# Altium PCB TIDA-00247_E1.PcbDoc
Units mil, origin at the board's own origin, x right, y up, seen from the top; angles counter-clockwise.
Board outline 550 x 2250 mil, 4 copper layers (Top Layer, GND, VCC, Bottom Layer), stack 90 mil thick; 72 components, 30 nets, 175 pads, 76 vias.
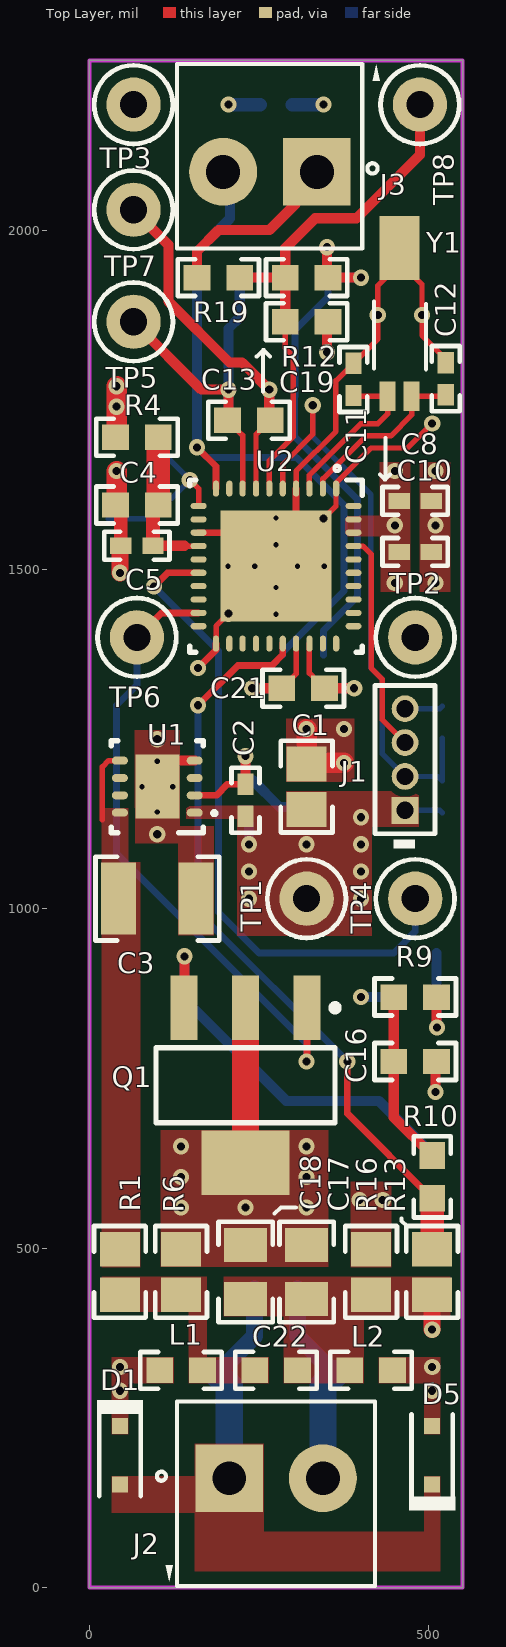
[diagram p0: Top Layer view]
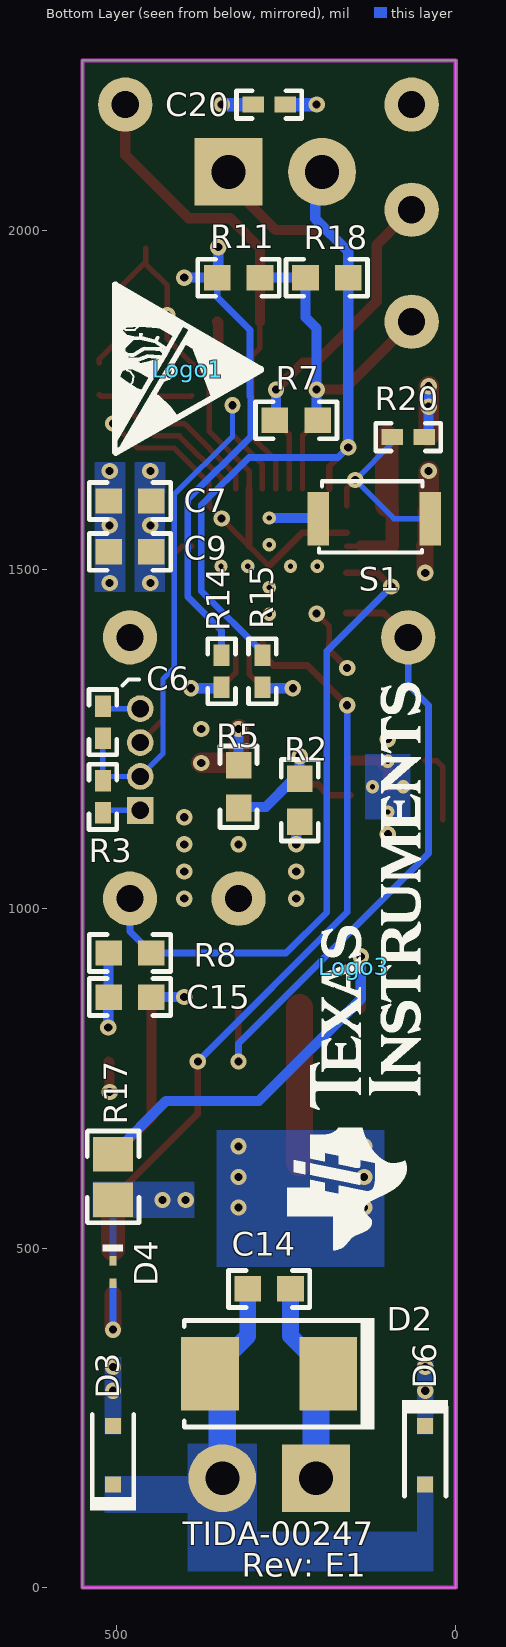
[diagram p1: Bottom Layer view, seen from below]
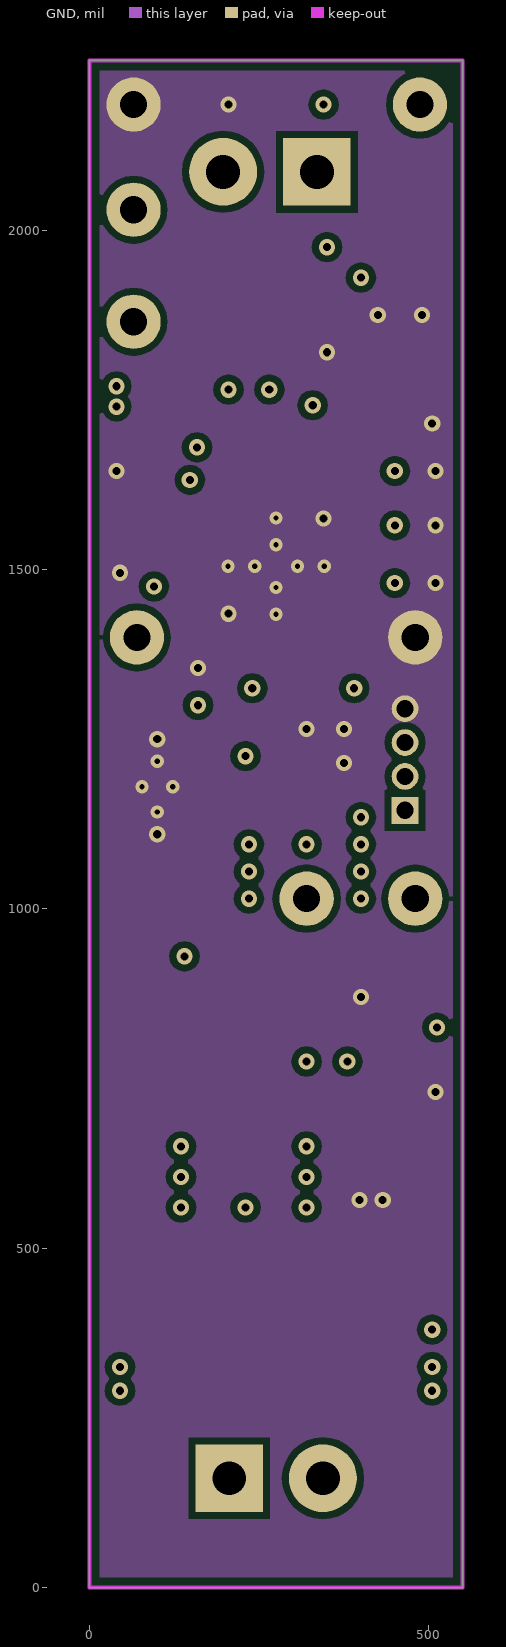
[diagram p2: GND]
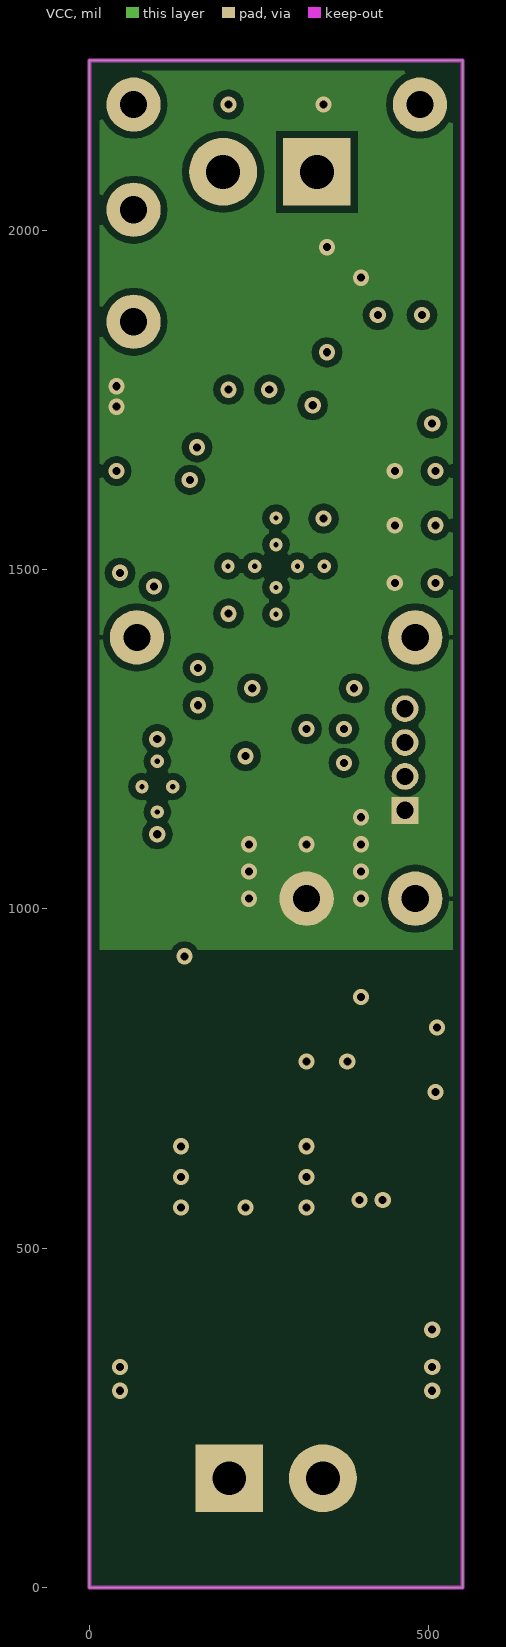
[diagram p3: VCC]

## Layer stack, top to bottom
Top Layer: signal copper 1.4
Dielectric: core 59.2, FR-4, Dk 4.8
GND: signal copper 1.4
Dielectric: prepreg 12.6, FR-4, Dk 4.8
VCC: signal copper 1.4
Dielectric: core 12.6, FR-4, Dk 4.8
Bottom Layer: signal copper 1.4

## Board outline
0,0 550,0 550,2250 0,2250

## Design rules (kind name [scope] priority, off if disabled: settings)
Clearance [All] p1: gap=10
DiffPairsRouting [All] p1: maxlimit=393.7 minlimit=4.92 mostfreqgap=5.91 maxuncoupledlength=500
FabricationTestPointUsage FabricationTestPointUsage_1 [All] p1: valid=0 allowmultiple=FALSE
FabricationTestpoint FabricationTestpoint_1 [All] p1: side=3 testpointundercomponent=TRUE minsize=40 maxsize=100 preferedsize=60 minholesize=0 maxholesize=40 preferedholesize=32 testpointgrid=1 allowsidetop=TRUE allowsidebottom=TRUE usegrid=TRUE gridtolerance=0.01
HoleSize [All] p1: absolutevalues=TRUE maxlimit=236.22 minlimit=7.87 maxpercent=80.000 minpercent=20.000
HoleSize FabricationTestpoint [All] p2 off: absolutevalues=TRUE maxlimit=100 minlimit=1 maxpercent=80.000 minpercent=20.000
HoleSize FabricationTestPointUsage [All] p3 off: absolutevalues=TRUE maxlimit=100 minlimit=1 maxpercent=80.000 minpercent=20.000
MinimumAnnularRing [All] p1: minimumring=5
PlaneClearance [All] p1: clearance=5
PlaneConnect [All] p1: planeconnectstyle=Direct reliefexpansion=15.75 reliefentries=4 reliefconductorwidth=5.91 reliefairgap=5.91
PolygonConnect [All] p1: connectstyle=Direct reliefconductorwidth=5.91 reliefentries=4 polygonreliefangle="90 Angle" airgapwidth=10
RoutingCorners [All] p1: cornerstyle=45-Degree minsetback=49.21 maxsetback=49.21
RoutingVias [All] p1: holewidth=12 width=24 viastyle="Through Hole" minholewidth=8 minwidth=18 maxholewidth=16 maxwidth=40
SilkscreenOverComponentPads [All] p1: minsilkscreentomaskgap=10
SolderMaskExpansion [All] p1: expansion=2.5
Width [All] p1: maxlimit=100 minlimit=6 preferedwidth=6
20 further rules are at their usual default settings.

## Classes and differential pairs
component class Header: J1
component class Sheet-1: C1 C2 C3 C4 C5 C6 C7 C8 C9 C10 C11 C12 C13 C14 C15 C16 C17 C18 C19 C20 C21 C22 D1 D2 D3 D4 D5 D6 H1 J1 J2 J3 L1 L2 Q1 R1 R2 R3 R4 R5 R6 R7 R8 R9 R10 R11 R12 R13 R14 R15 R16 R17 R18 R19 R20 S1 TP1 TP2 TP3 TP4 TP5 TP6 TP7 TP8 U1 U2 Y1
component class Hardware_ANSI-B: Logo1 ZZ1 ZZ2 ZZ3 ZZ4
component class AssemblyNote: ZZ1 ZZ2 ZZ3 ZZ4
component class Logo: Logo1

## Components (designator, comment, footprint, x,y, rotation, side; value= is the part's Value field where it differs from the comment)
C1 "GRM21BR71A475KA73L" 0805 320,1180 r90 top
C2 "GRM155R70J103KA01D" 0402 230,1160 r90 top
C3 "GRM32MR72A474KA01L" 1210 100,1015 r0 top
C4 "GRM188R71A225KE15D" 0603 70,1595 r180 top
C5 "GRM155R70J104KA01D" 0402 70,1535 r180 top
C6 "GRM155R70J222KA01D" 0402 520,1275 r90 bottom
C7 "GRM188R71A225KE15D" 0603 480,1601 r0 bottom
C8 "GRM155R70J104KA01D" 0402 480,1601 r0 top
C9 "GRM188R71A225KE15D" 0603 480,1526 r0 bottom
C10 "GRM155R70J104KA01D" 0402 480,1526 r0 top
C11 "GRM1555C1H100JA01D" 0402 389,1780 r90 top
C12 "GRM1555C1H100JA01D" 0402 525,1781.26 r90 top
C13 "GRM188R70J224KA88D" 0603 235,1720 r180 top
C14 "CAP, CERM, 0.01uF, 100V, +/-10%, X7R, 0603" 0603 275,440 r0 bottom
C15 "GRM188R70J105KA01D" 0603 480,870 r180 bottom
C16 "GRM188R70J105KA01D" 0603 480,775 r0 top
C17 "08055C105KAT2A" 0805_HV 320,465 r270 top
C18 "08055C103JAT2A" 0805_HV 230,465 r270 top
C19 "C0603C475K9PACTU" 0603 320,1865 r0 top
C20 "GRM155R70J104KA01D" 0402 275,2185 r0 bottom
C21 "GRM188R70J105KA01D" 0603 315,1325 r180 top
C22 "CAP, CERM, 0.01uF, 100V, +/-10%, X7R, 0603" 0603 275,320 r0 top
D1 "BAT46WJ,115" SOD-323F#1 45,195 r270 top
D2 "SM6T39CA" SMB 275,315 r0 bottom
D3 "BAT46WJ,115" SOD-323F#2 505,195 r90 bottom
D4 "ESD9R3.3ST5G" SOD-923 505,465 r270 bottom
D5 "BAT46WJ,115" SOD-323F#1 505,195 r90 top
D6 "BAT46WJ,115" SOD-323F#1 45,195 r270 bottom
J1 "850-10-004-10-001101" Preci-dip_850-xx-004-10-001101 465,1220 r90 top
J2 "ED555/2DS" TERM_BLK_ED555-2DS 206,161 r0 top
J3 "RTD Input" TERM_BLK_ED555-2DS 335,2086 r180 top
L1 "BLM18KG601SN1D" 0603 135,320 r180 top
L2 "BLM18KG601SN1D" 0603 415,320 r0 top
Logo1 "ESD Logo" ESD_Overlay_Medium 395,1795 r270 bottom
Logo3 "Texas Instruments" TI_Stacked_SolderMask_Small 150,915 r90 bottom (schematic designator Logo1)
Q1 "BCP55" SOT-223 230,740 r270 top
R1 "CRCW0805200RFKEA" 0805 45,465 r270 top
R2 "RG1608P-2212-B-T5" 0603 230,1160 r270 bottom
R3 "CRCW040247K0JNED" 0402 520,1165 r270 bottom
R4 "CRCW060310R0FKEA" 0603 70,1695 r180 top
R5 "RG1608P-1242-B-T5" 0603 320,1180 r270 bottom
R6 "CRCW0805100RFKEA" 0805 135,465 r270 top
R7 "RT0603BRD0725K5L" 0603 235,1720 r0 bottom
R8 "RT0603BRD0715K8L" 0603 480,935 r0 bottom
R9 "RT0603BRD0715K8L" 0603 480,870 r180 top
R10 "RT0603BRD07240KL" 0603 505,605 r270 top
R11 "RT0603BRD0710KL" 0603 320,1930 r0 bottom
R12 "RT0603BRD0710KL" 0603 320,1930 r0 top
R13 "RT0805BRD0780K6L" 0805 505,465 r90 top
R14 "CRCW04024K99FKED" 0402 345,1350 r90 bottom
R15 "CRCW04024K99FKED" 0402 285,1350 r90 bottom
R16 "RT0805BRD0740R2L" 0805 415,465 r270 top
R17 "CRCW080520R0FKEA" 0805 505,605 r90 bottom
R18 "RT0603BRD071KL" 0603 190,1930 r0 bottom
R19 "RT0603BRD071KL" 0603 190,1930 r0 top
R20 "CRCW04021M00JNED" 0402 70,1695 r180 bottom
S1 "SKRKAEE010" SW_SKRKAEE010 120,1575 r180 bottom
TP1 "5002" Keystone5002 320,1015 r0 top
TP2 "5001" Keystone5001 480,1400 r0 top
TP3 "5001" Keystone5001 65,2185 r0 top
TP4 "5000" Keystone5000 480,1015 r0 top
TP5 "5000" Keystone5000 65,1865 r0 top
TP6 "5000" Keystone5000 70,1400 r0 top
TP7 "5000" Keystone5000 65,2030 r0 top
TP8 "5000" Keystone5000 487,2185 r0 top
U1 "TPS7A1601DRB" DRB0008B 100,1180 r180 top
U2 "MSP430F2274IRHA" RHA0040B 275,1505 r270 top
Y1 "MS3V-T1R" CRYSTAL-MS3V-T1R 457,1816 r90 top
ZZ1 "This Assembly Note is for PCB labels only" AssemblyNoteLabel 144.43,3724.68 r0 top
ZZ2 "These assemblies are ESD sensitive, ESD precautions shall be observed." AssemblyNote 142.37,3647.98 r0 top
ZZ3 "These assemblies must be clean and free from flux and all contaminants. Use of no clean flux is not acceptable." AssemblyNote 144.39,3796.83 r0 top
ZZ4 "These assemblies must comply with workmanship standards IPC-A-610 Class 2, unless otherwise specified." AssemblyNote 145.73,3859.22 r0 top

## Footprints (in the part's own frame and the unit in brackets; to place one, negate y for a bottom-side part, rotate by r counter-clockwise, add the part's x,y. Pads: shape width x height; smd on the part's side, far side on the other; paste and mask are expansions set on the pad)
0402 [mm] "0402 from SM-752 data"
  rect 0.8x0.6 smd: 1(-0.6,0) 2(0.6,0)
  silkscreen extent -1.22,-0.52 1.22,0.52, body extent -0.55,-0.3 0.55,0.3, height 0.6
0603 [mm] "0603 from SM-752 data"
  rect 1x0.95 smd: 1(-0.8,0) 2(0.8,0)
  silkscreen extent -1.52,-0.69 1.52,0.69, body extent -0.87,-0.47 0.87,0.47, height 0.85
0805 [mm] "0805 from SM-752 data"
  rect 1.3x1.5 smd: 1(-0.85,0) 2(0.85,0)
  silkscreen extent -1.72,-0.97 1.72,0.97, body extent -1.1,-0.72 1.1,0.72, height 1.1
0805_HV [mil] "0805 with 30mil clearance between pads"
  rect 50x63 smd: 1(-40,0) 2(40,0)
  silkscreen extent -74,-40 74,40, body extent -43,-29 43,29, height 43
1210 [mm] "1210 from SM-752 data"
  rect 1.3x2.7 smd: 1(-1.45,0) 2(1.45,0)
  silkscreen extent -2.32,-1.57 2.32,1.57, body extent -1.7,-1.35 1.7,1.35, height 1.35
AssemblyNote [mil] "Assembly Note"
AssemblyNoteLabel [mil] "Assembly Note for PCB Labels"
CRYSTAL-MS3V-T1R [mm]
  rect 1.1x0.6 smd: 1(-1.55,-0.45) 2(-1.55,0.45)
  rect 2.4x1.5 smd: 3(4,0)
DRB0008B [mm] "SON, 8-Leads, Body 3x3mm, Pitch 0.65mm, Thermal Pad 2.4x1.65mm, TI Recommended"
  oval 0.6x0.3 smd: 1(-1.4,0.975) 2(-1.4,0.325) 3(-1.4,-0.325) 4(-1.4,-0.975) 5(1.4,-0.975) 6(1.4,-0.325) 7(1.4,0.325) 8(1.4,0.975)
  rect 1.65x2.4 smd paste-1.2: 9(0,0)
  silkscreen extent -1.73,-1.73 1.73,1.73, body extent -1.57,-1.57 1.58,1.58, height 1.01
ESD_Overlay_Medium [mil]
  silkscreen extent -127,-109 125,110
Keystone5000 [mil] "For Keystone 500x miniature loop terminals"
  round 80 hole 40: 1(0,0)
  silkscreen extent -58,-58 58,58, body extent -49,-49 49,49, height 182
Keystone5001 [mil] "For Keystone 500x miniature loop terminals"
  round 80 hole 40: 1(0,0)
  silkscreen extent -58,-58 58,58, body extent -49,-49 49,49, height 182
Keystone5002 [mil] "For Keystone 500x miniature loop terminals"
  round 80 hole 40: 1(0,0)
  silkscreen extent -58,-58 58,58, body extent -49,-49 49,49, height 182
Preci-dip_850-xx-004-10-001101 [mm] "Preci-dip"
  rect 1x1 hole 0.65: 1(-1.905,0)
  round 1 hole 0.65: 2(-0.635,0) 3(0.635,0) 4(1.905,0)
  silkscreen extent -3.32,-1.12 2.78,1.12, body extent -2.74,-1.1 2.74,1.1, height 5.2
RHA0040B [mm] "QFN, 40-Leads, Body 6x6mm, Pitch 0.5mm, Thermal Pad 4.15 x 4.15mm, TI Recommended"
  oval 0.6x0.23 smd mask+0.07: 1(-2.9,2.25) 2(-2.9,1.75) 3(-2.9,1.25) 4(-2.9,0.75) 5(-2.9,0.25) 6(-2.9,-0.25) 7(-2.9,-0.75) 8(-2.9,-1.25) 9(-2.9,-1.75) 10(-2.9,-2.25) 21(2.9,-2.25) 22(2.9,-1.75) 23(2.9,-1.25) 24(2.9,-0.75) 25(2.9,-0.25) 26(2.9,0.25) 27(2.9,0.75) 28(2.9,1.25) 29(2.9,1.75) 30(2.9,2.25)
  oval 0.23x0.6 smd mask+0.07: 11(-2.25,-2.9) 12(-1.75,-2.9) 13(-1.25,-2.9) 14(-0.75,-2.9) 15(-0.25,-2.9) 16(0.25,-2.9) 17(0.75,-2.9) 18(1.25,-2.9) 19(1.75,-2.9) 20(2.25,-2.9) 31(2.25,2.9) 32(1.75,2.9) 33(1.25,2.9) 34(0.75,2.9) 35(0.25,2.9) 36(-0.25,2.9) 37(-0.75,2.9) 38(-1.25,2.9) 39(-1.75,2.9) 40(-2.25,2.9)
  rect 4.15x4.15 smd paste-2.1 mask+0.07: 41(0,0)
  silkscreen extent -3.22,-3.22 3.22,3.22, body extent -3.08,-3.08 3.08,3.08, height 1.01
SMB [mil] "Molded Diode, 2-Leads, Body 5.4x3.6mm, IPC Medium Density, based on OnSemi component dimensions"
  rect 85x107.99 smd: 1(-87.01,0) 2(87.01,0)
  silkscreen extent -155,-82 125,82, body extent -106,-71 106,71, height 91
SOD-323F#1 [mm] "NXP recommended land pattern"
  rect 0.6x0.6 smd paste+0: 1(-1.1,0) 2(1.1,0)
  silkscreen extent -2.06,-0.86 1.53,0.87, body extent -1.35,-0.67 1.35,0.68, height 0.79
SOD-323F#2 [mm] "NXP recommended land pattern"
  rect 0.6x0.6 smd paste+0: 1(-1.1,0)
  rect 0.6x0.6 smd: 2(1.1,0)
  silkscreen extent -2.07,-0.86 1.53,0.86, body extent -1.35,-0.68 1.35,0.67, height 0.79
SOD-923 [mm] "ON-SEMI"
  rect 0.36x0.25 smd: 1(-0.42,0) 2(0.42,0)
  silkscreen extent -1.02,-0.39 -0.76,0.37, body extent -0.45,-0.35 0.45,0.35, height 0.44
SOT-223 [mm] "SOT223/SC73, 4-Leads, Body 6.5x3.5mm, Pitch 2.3mm, Lead Span 7mm, IPC Medium Density"
  rect 2.4x1 smd: 1(-2.9,2.3) 2(-2.9,0) 3(-2.9,-2.3)
  rect 2.4x3.3 smd: 4(2.9,0)
  silkscreen extent -3.02,-3.35 1.4,3.48, body extent -3.5,-3.25 3.5,3.25, height 1.62
SW_SKRKAEE010 [mm] "Alps recommended land pattern"
  rect 0.8x2 smd: 1(-2.1,0) 2(2.1,0)
  body extent -2.4,-1.45 2.4,1.45, height 1.96
TERM_BLK_ED555-2DS [mil]
  rect 100x100 hole 50: 1(0,0)
  round 100 hole 50: 2(138,0)
  silkscreen extent -94,-159 215,113, body extent -69,-150 207,106, height 323
TI_Stacked_SolderMask_Small [mil]
  silkscreen extent -418,-98 418,98

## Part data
C1: "CAP, CERM, 4.7 µF, 10 V, +/- 10%, X7R, 0805"
C2: "CAP, CERM, 0.01 µF, 6.3 V, +/- 10%, X7R, 0402"
C3: "CAP, CERM, 0.47 µF, 100 V, +/- 10%, X7R, 1210"
C4 C7 C9: "CAP, CERM, 2.2 µF, 10 V, +/- 10%, X7R, 0603"
C5 C8 C10 C20: "CAP, CERM, 0.1 µF, 6.3 V, +/- 10%, X7R, 0402"
C6: "CAP, CERM, 2200pF, 6.3V, +/-10%, X7R, 0402"
C11 C12: "CAP, CERM, 10pF, 50V, +/-5%, C0G/NP0, 0402"
C13: "CAP, CERM, 0.22 µF, 6.3 V, +/- 10%, X7R, 0603"
C14 C22: library part GRM188R72A103KA01D
C15 C16 C21: "CAP, CERM, 1 µF, 6.3 V, +/- 10%, X7R, 0603"
C17: "CAP, CERM, 1uF, 50V, +/-10%, X7R, 0805"
C18: "CAP, CERM, 0.01uF, 50V, +/-5%, X7R, 0805"
C19: "CAP, CERM, 4.7 µF, 6.3 V, +/- 10%, X5R, 0603"
D1 D3 D5 D6: "Diode, Schottky, 100V, 0.25A, SOD-323F"
D2: library part SMBJ40CA-13-F, "TVS DIODE 33.3VWM 69.7VC SMB"
D4: "Diode, TVS, Uni, 3.3V, 0.15W, SOD-923"
J1: "Header, 50mil, 4x1, Gold, TH"
J2: "Terminal Block, 6A, 3.5mm Pitch, 2-Pos, TH"
J3: library part ED555/2DS, "Terminal Block, 6A, 3.5mm Pitch, 2-Pos, TH"
L1 L2: "Ferrite Bead, 600 ohm @ 100MHz, 1.3A, 0603"
Logo1 Logo3: library part TI_Logo, "Texas Instrument Corporate Signature"
Q1: library part "BCP55, Fairchild Semiconductor", "Transistor, NPN, 60 V, 1.5 A, SOT-223"
R1: "RES, 200 ohm, 1%, 0.125W, 0805"
R2: "RES, 22.1 k, 0.1%, 0.1 W, 0603"
R3: "RES, 47k ohm, 5%, 0.063W, 0402"
R4: "RES, 10.0 ohm, 1%, 0.1W, 0603"
R5: "RES, 12.4 k, 0.1%, 0.1 W, 0603"
R6: "RES, 100 ohm, 1%, 0.125W, 0805"
R7: "RES, 25.5 k, 0.1%, 0.1 W, 0603"
R8 R9: "RES, 15.8 k, 0.1%, 0.1 W, 0603"
R10: "RES, 240 k, 0.1%, 0.1 W, 0603"
R11 R12: "RES, 10.0 k, 0.1%, 0.1 W, 0603"
R13: "RES, 80.6k ohm, 0.1%, 0.125W, 0805"
R14 R15: "RES, 4.99 k, 1%, 0.063 W, 0402"
R16: "RES, 40.2, 0.1%, 0.125 W, 0805"
R17: "RES, 20.0 ohm, 1%, 0.125W, 0805"
R18 R19: "RES, 1.00 k, 0.1%, 0.1 W, 0603"
R20: "RES, 1.0 M, 5%, 0.063 W, 0402"
S1: "Switch, Push Button, SMD"
TP1: "Test Point, Miniature, White, TH"
TP2 TP3: "Test Point, Miniature, Black, TH"
TP4 TP5 TP6 TP7 TP8: "Test Point, Miniature, Red, TH"
U1: "60-V, 5-µA IQ, 100-mA, Low-Dropout Voltage Regulator with Enable and Power-Good, DRB0008B"
U2: "16-bit Ultra-Low-Power Microcontroller, 32 KB Flash, 1 K RAM, RHA0040B"
Y1: library part CRYSTAL_MS3V-T1R, "Crystal, Tuning Fork, 30kHz - 200kHz, SMD"
ZZ1: library part AssemblyNoteLabel
ZZ2 ZZ3 ZZ4: library part AssemblyNote

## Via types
v1: diameter 24, hole 12, Top Layer to Bottom Layer, tented both sides, 64 vias
v2: diameter 19.68, hole 7.87, Top Layer to Bottom Layer, tented both sides, 12 vias

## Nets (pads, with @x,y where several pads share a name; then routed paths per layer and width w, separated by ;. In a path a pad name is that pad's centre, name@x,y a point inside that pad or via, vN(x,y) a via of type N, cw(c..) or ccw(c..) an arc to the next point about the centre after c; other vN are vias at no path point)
3.3V: C1.1 C2.1 C7.1 C8.1 C9.1 C10.1 C20.2 J1.1 R2.2 R3.2 R4.2 R11.2 R12.2 R14.2 R20.2 TP1.1 U1.1 U2.38 U2.39 | length 1108.3
  Top Layer w15: R12.2@350,1931.5 v1(350,1975) ; R12.2 v1(400,1930)
  Top Layer w30: R4.2@40,1696.5 v1(40,1740) v1(40,1770)
  Bottom Layer w8: J1.1 516.38,1145 R3.2
  Bottom Layer w10: R14.2 345,1410 395,1460 395,1603.13 302,1696.13 302,1754.18 303,1755.18 303,1853 351.5,1901.5 R11.2
  Bottom Layer w15: v1(40,1770) v1(40,1740) 40,1701.38 R20.2 ; R2.2@230,1130 235,1125 v1(235,1095) ; R11.2@350,1931.5 v1(350,1975) ; R11.2@356.5,1930 v1(400,1930)
  Bottom Layer w20: C20.2 v1(345,2185) ; R11.2@350,1931.5 R11.2
  other v1: 235,1015 400,1015 235,1055 400,1055 320,1095 400,1095 400,1135 450,1480 450,1565 450,1645
ADC_IN: C13.1 R7.2 TP7.1 U2.7 | length 559.6
  Top Layer w8: U2.7 245.47,1698.98 C13.1
  Top Layer w15: TP7.1 116.32,1978.68 116.32,1895 206.32,1805 225,1805 v1(265,1765) 265,1721.5 C13.1
  Bottom Layer w15: v1(265,1765) 265,1721.5 R7.2
AVCC: C4.1 C5.1 R4.1 U2.14 | length 230.7
  Top Layer w8: 140,1535 140.47,1534.53 U2.14
  Top Layer w15: C5.1 140,1535
  Top Layer w20: C5.1 93.62,1587.13 C4.1
  Top Layer w35: C4.1 R4.1
BASE_BJT: Q1.1 TP6.1 U2.19 | length 938.6
  Top Layer w10: TP6.1 106.1,1436.1 U2.19 ; v1(320,775) 320.55,775.55 Q1.1
  Bottom Layer w10: TP6.1 70,1330 40,1300 40,1081.72 320,801.72 v1(320,775)
BRDG_OA0+: C19.1 R12.1 R19.2 TP8.1 U2.6 | length 770.1
  Top Layer w8: U2.6 265.16,1660.48 300.18,1695.5 300.18,1814.5 288.5,1826.18 C19.1
  Top Layer w15: R19.2 R12.1 ; C19.1 R12.1 ; TP8.1 487,2111 393.5,2017.5 332.5,2017.5 288.5,1973.5 R12.1
BRDG_OA0-: C13.2 R7.1 R11.1 R18.2 TP5.1 U2.8 | length 621.6
  Top Layer w8: C13.2 225.79,1697.72 U2.8
  Top Layer w15: TP5.1 165,1765 v1(205,1765) 205,1721.5 C13.2
  Bottom Layer w15: R7.1 205,1721.5 v1(205,1765) 205,1855 221.5,1871.5 R18.2 R11.1
BRDG_ON/OFF: J3.2 R15.2 R18.1 U2.10 | length 1007.7
  Top Layer w10: v1(158.5,1680) 186.42,1652.09 U2.10
  Bottom Layer w10: v1(158.5,1680) 173.5,1665 304.85,1665 375,1594.85 375,1468.28 285,1378.28 R15.2
  Bottom Layer w15: v1(158.5,1680) R18.1 158.5,1968.5 207,2017 J3.2@207,2085
LDO_IN: C22.1 L1.1 R1.2 R6.2
LOOP+: C14.1 D1.2 D2.1 D5.1 J2.1 | length 309.5
  Bottom Layer w25: D2.1 243.5,370.51 C14.1
  Bottom Layer w40: D2.1 206,296.99 J2.1
LOOP-: C14.2 D2.2 D3.1 D6.2 J2.2 | length 309.5
  Bottom Layer w25: C14.2 306.5,370.51 D2.2
  Bottom Layer w40: J2.2 344,296.99 D2.2
NetC2_2: C2.2 R2.1 R5.2 U1.2 | length 264.6
  Top Layer w10: U1.2 187.2,1167.2 203.62,1183.62 C2.2
  Top Layer w15: C2.2 v1(230,1225)
  Bottom Layer w15: v1(230,1225) 230,1190 240,1190 280,1150 R5.2@320,1150
NetC3_1: C3.1 R1.1 U1.5 U1.8 | length 107.8
  Top Layer w8: 19.07,1130.93 19.07,1209.07 28.39,1218.39 U1.5
NetC15_1: C15.1 R8.2 R9.1 | length 155.8
  Top Layer w15: v1@510,825 511.5,826.5 R9.1
  Bottom Layer w15: R8.2 C15.1 512,869.5 v1(512,825)
NetC16_1: C16.1 R9.2 R10.1 | length 256.9
  Top Layer w15: R9.2 C16.1 448.5,692.99 R10.1
NetC17_1: C17.1 C18.1 Q1.2 Q1.4 R6.1 | length 228.3
  Top Layer w40: Q1.4 Q1.2
  other v1: 135,560 230,560 320,560 135,605 320,605 135,650 320,650
NetC17_2: C17.2 C18.2 C22.2 D4.2 L2.1 R13.1 R16.2 | length 120
  Top Layer w25: v1(505,380) R13.1
  Bottom Layer w10: v1(505,380) D4.2
NetD1_1: D1.1 D6.1 L1.2
  other v1: 45,290 45,325
NetD3_2: D3.2 D5.2 L2.2
  other v1: 505,290 505,325
NetJ3_1: J3.1 R19.1 | length 276.2
  Top Layer w15: R19.1 158.5,1968.5 190,2000 265,2000 345,2080 J3.1@345,2085
NetQ1_3: Q1.3 R17.2 | length 598.7
  Top Layer w15: Q1.3 140,854.72 v1(140,930)
  Bottom Layer w15: v1(140,930) 140,867 290,717 426.46,717 R17.2
NetR20_1: R20.1 S1.2 U2.11 | length 273.6
  Top Layer w8: v1(148.03,1631.97) 160.83,1619.17 U2.11
  Bottom Layer w8: S1.2@27.32,1575 S1.2 91.06,1575 v1(148.03,1631.97) 93.62,1686.38 R20.1
PWM_OUT: R8.1 TP4.1 U2.16 | length 969.9
  Top Layer w10: v1(95,1475) 115.16,1495.16 U2.16
  Bottom Layer w10: v1(95,1475) 190,1380 190,995 250,935 R8.1 480,966.5 TP4.1
SBWTCK: J1.3 U2.37 | length 329
  Top Layer w8: U2.37 402.97,1534.53 414.98,1522.52 414.98,1355.02 431.31,1338.69 431.31,1278.69 J1.3
SBWTDIO: C6.1 J1.2 R3.1 U2.5 | length 864.7
  Top Layer w8: U2.5 284.84,1654.71 329,1698.86 v1(329,1742)
  Bottom Layer w8: v1(329,1742) 329,1696 414.82,1610.18 414.82,1550.68 ; 414.82,1550.5 414.82,1355.18 431.31,1338.69 431.31,1228.69 J1.2 513.62,1195 R3.1 C6.1
VEREF+: C21.1 R14.1 U2.28 | length 164.1
  Top Layer w8: U2.28 324.21,1347.28 C21.1
  Top Layer w15: C21.1 v1(390,1325)
  Bottom Layer w15: R14.1 346.38,1325 v1(390,1325)
VEREF-: C21.2 R15.1 U2.27 | length 163.6
  Top Layer w8: C21.2 304.53,1346.02 U2.27
  Top Layer w15: v1(240,1325) C21.2
  Bottom Layer w15: v1(240,1325) 283.62,1325 R15.1
VTOI_OA1+: R10.2 R13.2 U2.26 | length 1116.3
  Top Layer w10: v1(160,1300) 218.7,1358.7 268.7,1358.7 284.84,1374.84 U2.26 ; v1(380,775) 380,698.5 R10.2
  Top Layer w35: R13.2 R10.2
  Bottom Layer w10: v1(160,1300) 160,995 v1(380,775)
VTOI_OA1-: C1.2 C3.2 C4.2 C5.2 C6.2 C7.2 C8.2 C9.2 C10.2 C11.2 C12.2 C15.2 C16.2 C19.2 C20.1 D4.1 J1.4 R5.1 R16.1 R17.1 S1.1 TP2.1 TP3.1 U1.4 U1.9 U2.1 U2.4 U2.13 U2.21 U2.41 Y1.3 | length 1956.9
  Top Layer w8: U2.21@186.64,1391.05 186.64,1416.64 v1(205,1435) ; U2.41 304.53,1534.53 v1(345,1575) 363.36,1593.36 363.36,1618.95 U2.1 363.58,1627.58 415,1679 469,1679 v1(505,1715) ; U2.4 304.53,1644.98 363.19,1703.64 363.19,1777.93 388.89,1803.62 C11.2 425,1839.62 425,1918.23 457,1950.23 Y1.3@457,1953 ; Y1.3 Y1.3@457,1953 ; C12.2 525,1809.88 490,1844.88 490,1920 Y1.3@457,1953
  Top Layer w10: v1(160,1355) 186.42,1381.42 U2.21 ; U2.13 225.79,1554.21 U2.41 ; U2.41@304.53,1534.53 U2.4
  Top Layer w15: U1.9 100,1205 113.39,1218.39 U1.4 ; v1(350,1820) 350,1863.5 C19.2 ; v1(510,730) 510,773.5 C16.2
  Top Layer w20: C5.2 C4.2@46.38,1587.13
  Top Layer w25: C4.2 C4.2@40,1596.5 ; v1(45,1495) 45,1533.62 C5.2
  Top Layer w30: C4.2@40,1596.5 v1(40,1645) ; C1.2@318.46,1215 C1.2 ; v1(320,1265) C1.2 ; v1(375,1215) 321.54,1215 C1.2
  Bottom Layer w8: J1.4 516.38,1295 C6.2
  Bottom Layer w15: S1.1 203.54,1575.87 v2(275,1575.87) ; R5.1@320,1210 v1(320,1265) ; v1(400,870) C15.2
  Bottom Layer w20: v1(205,2185) C20.1
  other v1: 398,571 432,571 100,1110 100,1250 375,1265 510,1480 510,1565 510,1645 425,1875 490,1875
  other v2: 100,1142.6 77.36,1180 122.64,1180 100,1217.4 275,1434.13 275,1473.5 204.13,1505 243.5,1505 306.5,1505 345.87,1505 275,1536.5
XIN: C11.1 U2.3 Y1.2 | length 249
  Top Layer w8: U2.3 324.21,1639.21 400,1715 425,1715 439.28,1729.28 Y1.2 390.4,1754.98 C11.1
XOUT: C12.1 U2.2 Y1.1 | length 254.7
  Top Layer w8: U2.2 343.9,1633.44 407.46,1697 444,1697 474.72,1727.72 Y1.1 ; Y1.1@482.72,1755.24 522.6,1755.24 C12.1
pads on no net: U1.3 U1.6 U1.7 U2.9 U2.12 U2.15 U2.17 U2.18 U2.20 U2.22 U2.23 U2.24 U2.25 U2.29 U2.30 U2.31 U2.32 U2.33 U2.34 U2.35 U2.36 U2.40

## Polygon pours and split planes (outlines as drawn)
LDO_IN on Top Layer "Top Layer-No Net 2" (solid, remove dead copper, pour order 35): 15,458 15,406 146,406 146,301 264,301 264,339 173,339 173,458
VTOI_OA1- on Top Layer "Top Layer-No Net 8" (solid, remove dead copper, pour order 27): 385,472 445,472 445,598 385,598 385,472
3.3V on Top Layer "Top Layer-No Net 7" (solid, remove dead copper, pour order 44): 143,1152 143,1133 218,1133 218,960 416,960 416,1121 485,1121 485,1173 290,1173 290,1152
VTOI_OA1- on Top Layer "Top Layer-No Net 10" (solid, remove dead copper, pour order 50): 290,1280 290,1187 390,1187 390,1280 290,1280
VTOI_OA1- on Top Layer "Top Layer-No Net 9" (solid, remove dead copper, pour order 49): 133,1263 67,1263 67,1097 131,1097 131,961 183,961 183,1122 133,1122 133,1263
NetC17_2 on Top Layer "Top Layer-No Net 3" (solid, remove dead copper, pour order 36): 286,301 404,301 404,400 535,400 535,458 198,458 198,400 286,400
VTOI_OA1- on Top Layer "Top Layer-No Net 6" (solid, remove dead copper, pour order 42): 487,1658 532,1658 532,1579 532,1549 532,1467 487,1467
3.3V on Top Layer "Top Layer-No Net 6" (solid, remove dead copper, pour order 43): 473,1658 428,1658 428,1579 377,1579 377,1549 428,1549 428,1467 473,1467
NetC3_1 on Top Layer "Top Layer-No Net 5" (solid, remove dead copper, pour order 39): 75,472 15,472 15,1148 57,1148 57,1069 75,1069
NetC17_1 on Top Layer "Top Layer-No Net 4" (solid, remove dead copper, pour order 38): 105,473 105,674 352,674 352,473
NetD3_2 on Top Layer "Top Layer-No Net 1" (solid, remove dead copper, pour order 33): 517,226 517,339 426,339 426,301 493,301 493,226
NetD1_1 on Top Layer "Top Layer-No Net 1" (solid, remove dead copper, pour order 34): 33,226 33,339 124,339 124,301 57,301 57,226
LOOP+ on Top Layer "Top Layer-No Net" (solid, remove dead copper, pour order 31): 155,24 517,24 517,164 493,164 493,82 257,82 257,212 155,212
LOOP+ on Top Layer "Top Layer-No Net" (solid, remove dead copper, pour order 32): 257,110 33,110 33,164 155,164 155,212 257,212 257,110
NetD3_2 on Bottom Layer "Bottom Layer-No Net 2" (solid, remove dead copper, pour order 29): 493,339 493,226 517,226 517,339
NetD1_1 on Bottom Layer "Bottom Layer-No Net 2" (solid, remove dead copper, pour order 30): 33,339 33,226 57,226 57,339
VTOI_OA1- on Bottom Layer "Bottom Layer-No Net 1" (solid, remove dead copper, pour order 46): 535,598 385,598 385,545 500,545 500,474 510,474 510,545 535,545
VTOI_OA1- on Bottom Layer "Bottom Layer-No Net" (solid, remove dead copper, pour order 45): 67,1228 67,1132 133,1132 133,1228
NetC17_1 on Bottom Layer "Top Layer-No Net 4" (solid, remove dead copper, pour order 37): 105,473 105,674 352,674 352,473
3.3V on Bottom Layer "Top Layer-No Net 6" (solid, remove dead copper, pour order 40): 473,1658 428,1658 428,1579 428,1549 428,1467 473,1467
VTOI_OA1- on Bottom Layer "Top Layer-No Net 6" (solid, remove dead copper, pour order 41): 487,1658 532,1658 532,1579 532,1549 532,1467 487,1467
LOOP- on Bottom Layer "Top Layer-No Net" (solid, remove dead copper, pour order 26): 395,24 33,24 33,164 57,164 57,82 293,82 293,212 395,212
LOOP- on Bottom Layer "Top Layer-No Net" (solid, remove dead copper, pour order 28): 293,110 517,110 517,164 395,164 395,212 293,212 293,110
VTOI_OA1- on GND "GND-No Net" (solid, remove dead copper, pour order 48): 15,15 535,15 535,2235 15,2235
3.3V on VCC "GND-No Net" (solid, remove dead copper, pour order 47): 15,940 535,940 535,2235 15,2235

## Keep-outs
Keep-Out Layer:
  the board outline again, w6
  text ".Layer_Name" at 575.52,-858.49 h60

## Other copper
Top Layer:
  text ".Layer_Name" at 575.52,-858.49 h60
GND:
  text "Layer2_GND Plane" at 596.16,-861 h60
VCC:
  text "Layer3_VCC Plane" at 596.77,-860.93 h60
Bottom Layer:
  text ".Layer_Name" at 575.52,-858.49 h60

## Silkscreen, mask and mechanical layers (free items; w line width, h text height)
Top Overlay:
  circle w6: c417,2090.99 r7.61
  circle w6: c365,1649 r4
  circle w6: c184,1141 r3
  circle w6: c106,164 r6.71
  lines w6: 246,1814 247,1814 256,1823 ; 256,1762 256,1823 ; 266,1814 257,1823 256,1823 ; 273,551 282,560 304,560 ; 419,1796 419,1895 ; 428,1640 435,1633 436,1633 ; 436,1694 436,1633 ; 443,1640 436,1633 ; 460,544 460,540.2 467.6,532.6 ; 496,1795 496,1891
  text ".Layer_Name" at 575.52,-858.49 h60
Bottom Overlay:
  lines w6: 49,1622.39 49,1630 197,1630 197,1622.68 ; 49.71,1528.94 49.71,1525 201.28,1525 201.28,1530.91 ; 467,1338 482,1338 491,1329
  text "TIDA-00247" at 402,62 h35
  text "Rev: E1" at 315,16 h35
  text ".Layer_Name" at 575.52,-858.49 h60
Top Paste:
  text ".Layer_Name" at 575.52,-858.49 h60
Bottom Paste:
  text ".Layer_Name" at 575.52,-858.49 h60
Top Solder:
  text ".Layer_Name" at 575.52,-858.49 h60
  text ".Layer_Name" at 575.52,-858.49 h60
Bottom Solder:
  text ".Layer_Name" at 575.52,-858.49 h60
Drill Guide:
  text ".Layer_Name" at 575.52,-858.49 h60
M1 Board Outline:
  the board outline again, w6
  text "Board Outline" at 635,-865 h60
M2 Board Dimensions:
  rectangle: 123.02,-410.5 498.02,-285.5
  rectangle: -1.98,-285.5 123.02,-160.5
  lines w7: -1.98,-285.5 998.02,-285.5 ; 123.02,-410.5 123.02,-160.5 ; 248.02,-410.5 248.02,-160.5 ; 498.02,-410.5 498.02,-160.5 ; 748.02,-410.5 748.02,-160.5 ; -1.98,-410.5 -1.98,-160.5 998.02,-160.5 998.02,-410.5 -1.98,-410.5
  lines w10: -1.98,-475.5 -1.98,-455.5 ; 58.02,-485.5 -1.98,-465.5 ; 58.02,-445.5 -1.98,-465.5 ; 222.1,-465.5 -1.98,-465.5 ; 773.94,-465.5 998.02,-465.5 ; 938.02,-485.5 998.02,-465.5 ; 938.02,-445.5 998.02,-465.5 ; 998.02,-475.5 998.02,-455.5
  text "1000 (mil)" at 232.1,-501.49 h60
M3 3D STEP Top:
  text ".Layer_Name" at 575.52,-858.49 h60
M4 3D STEP Bottom:
  text ".Layer_Name" at 575.52,-858.49 h60
M5 Assembly Top:
  circle w6: c386,2082 r9.22
  circle w6: c490,1701 r7.07
  circle w6: c465,1126 r7.07
  circle w6: c153,159 r9.49
  circle w6: c321,894 r4.47
  lines w10: -293.48,-930.17 6306.52,-930.17 ; -293.48,-726.83 6308.52,-726.83 ; -293.48,-523.5 -293.48,-1133.5 3711.52,-1133.5 6308.52,-1133.5 6308.52,-523.5 -292.98,-523.5 -292.98,-1133.5 1282.52,-1133.5 ; 2171.52,-1133.5 2171.52,-523.5 ; 3438.52,-726.83 3438.52,-523.5 ; 4278.52,-726.83 4278.52,-523.5 ; 4900.52,-1140 4900.52,-937.17
  text "COMPONENTS MARKED 'DNP' SHOULD NOT BE POPULATED." at 1152.02,-318.5 h60
  text "ASSEMBLY VARIANT:" at 1151.52,-434 h60
  text ".VariantName" at 2187.52,-434 h60
  text "PCB VIEWED FROM TOP SIDE" at -229.98,-655.67 h60
  text "BOARD #:" at 2246.52,-655.67 h60
  text ".PRJ_Number" at 2792.02,-655.67 h60
  text "SVN REV:" at 4474.52,-655.67 h60
  text ".VersionControl_RevNumber" at 4980.52,-655.67 h60
  text "REV:" at 3560.52,-667 h60
  text ".PCB_Rev" at 3896.52,-667 h60
  text "LAYER  NAME =" at -229.98,-858.49 h60
  text "ASSEMBLY TOP" at 600.52,-864.34 h60
  text "PLOT NAME =" at -229.98,-1064.34 h60
  text ".plot_File_Name" at 575.52,-1064.34 h60
  text "GENERATED    :" at 2248.52,-1064.34 h60
  text ".Print_Date" at 3118.02,-1064.34 h60
  text ".Print_Time" at 3847.02,-1064.34 h60
  text "TEXAS INSTRUMENTS" at 5111.52,-1064.34 h60
M6 Assembly Bottom:
  lines w10: -293.98,-727.33 6308.02,-727.33 ; -291.98,-930.67 6308.02,-930.67 ; 1114.02,-1140.5 1114.02,-937.67 ; 1736.02,-727.33 1736.02,-524 ; 2576.02,-727.33 2576.02,-524 ; 3843.02,-1134 3843.02,-524 ; 4732.02,-1134 6307.52,-1134 6307.52,-524 -293.98,-524 -293.98,-1134 2303.02,-1134 6308.02,-1134 6308.02,-524
  text "COMPONENTS MARKED 'DNP' SHOULD NOT BE POPULATED." at 6100.52,-318 h60
  text ".VariantName" at 5056.52,-434 h60
  text "ASSEMBLY VARIANT:" at 6095.52,-434 h60
  text ".PRJ_Number" at 3293.52,-654 h60
  text ".VersionControl_RevNumber" at 1034.02,-656.17 h60
  text "SVN REV:" at 1540.02,-656.17 h60
  text ".PCB_Rev" at 2086.52,-656.17 h60
  text "REV:" at 2378.02,-656.17 h60
  text "BOARD #:" at 3768.02,-656.17 h60
  text "PCB VIEWED FROM BOTTOM SIDE" at 6244.52,-656.17 h60
  text "LAYER  NAME =" at 2546.37,-858.49 h60
  text "ASSEMBLY BOTTOM" at 1723.02,-859.84 h60
  text "TEXAS INSTRUMENTS" at 903.02,-1064.84 h60
  text ".Print_Time" at 2167.52,-1064.84 h60
  text ".Print_Date" at 2896.52,-1064.84 h60
  text "GENERATED    :" at 3766.02,-1064.84 h60
  text ".plot_File_Name" at 5439.02,-1064.84 h60
  text "PLOT NAME =" at 6244.52,-1064.84 h60
M9 Title Sheet:
  drawing of 57 lines, arcs and shapes, not listed
  text "1" at 738.36,8036.5 h70
  text "2" at 3234.02,8036.5 h70
  text "3" at 5723.36,8036.5 h70
  text "4" at 8230.03,8036.5 h70
  text "5" at 10729.02,8036.5 h70
  text "6" at 13234.02,8036.5 h70
  text "A" at -417.98,6893.5 h70
  text "A" at 14382.02,6893.5 h70
  text "B" at -417.98,4513.5 h70
  text "B" at 14382.02,4513.5 h70
  text "C" at -417.98,2138.5 h70
  text "C" at 14382.02,2138.5 h70
  text "PROJECT TITLE:" at 11342.02,277.5 h45
  text ".PRJ_Title" at 11340,146 h100
  text "DESIGNED FOR:" at 11342.02,-23.5 h45
  text ".PRJ_Customer" at 11392.02,-163.5 h70
  text "D" at -417.98,-231.5 h70
  text "D" at 14382.02,-231.5 h70
  text "FILE NAME:" at 11342.02,-323.5 h45
  text ".PCB_File_Name_No_Path" at 11392.02,-443.5 h70
  text "Texas Instruments (TI) and/or its licensors do not warrant the accuracy or completeness of this specification" at 6372.52,-605.34 h45
  text "ENGINEER:" at 11342.02,-613.5 h45
  text "LAYOUT BY:" at 12847.02,-613.5 h45
  text "or any information contained therein. TI and/or its licensors do not warrant that this design will meet" at 6327.53,-718 h45
  text ".PRJ_Engineer" at 11392.02,-768.49 h70
  text "the specifications, will be suitable for your application or fit for any particular purpose, or will operate in" at 6327.53,-830.67 h45
  text "ALTIUM DESIGNER VERSION:" at 12847.02,-923.5 h45
  text "an implementation. TI and/or its licensors do not warrant that the design is production worthy. You should" at 6327.53,-943.33 h45
  text "completely validate and test your design implementation to confirm the system functionality for your application." at 6372.52,-1056 h45
  text ".print_Scale" at 11392.02,-1056.83 h70
  text ".Application_BuildNumber" at 12897.52,-1056.83 h70
  text "1" at 738.36,-1263.5 h70
  text "2" at 3234.02,-1263.5 h70
  text "3" at 5723.36,-1263.5 h70
  text "4" at 8230.03,-1263.5 h70
  text "5" at 10729.02,-1263.5 h70
  text "6" at 13234.02,-1263.5 h70
M10 Fab Notes:
  drawing of 220 lines, arcs and shapes, not listed
  text "DESIGN INFORMATION" at 12379.54,6810 h60
  text "(REFER ALSO ARRAY/PANEL PROFILING INFORMATION)" at 12017.98,6648.29 h60
  text "BOARD SIZE" at 11331.98,6644 h60
  text "550MIL" at 11723,6520 h60
  text "2250MIL" at 12470,6518 h60
  text "X" at 12299.98,6516.18 h60
  text "Number of Layers :" at 11674.98,6409 h60
  text "4" at 12769.79,6399 h60
  text "MIN. TRACK WIDTH:" at 11674.98,6270 h60
  text "8" at 12771.22,6270 h60
  text "MIL" at 12925.98,6270 h60
  text "MIN. CLEARANCE:" at 11674.98,6138 h60
  text "MIL" at 12925.98,6138 h60
  text "7.86" at 12682.52,6136 h60
  text "MIN. VIA PAD SIZE:" at 11674.98,6006 h60
  text "MIL" at 12925.98,6006 h60
  text "19.685" at 12570,6005 h60
  text "It is not an impedance controlled board." at 11375,5885 h60
  text "EXTERNAL" at 13189.52,5777 h60
  text "0.111mm (4.39MIL)" at 12384.98,5774.29 h60
  text "MINIMUM ANNULAR RING" at 11360.75,5770 h60
  text "PER" at 11560.75,5652 h60
  text "IPC-D-275 CLASS 2 LEVEL C" at 11780.75,5652 h60
  text "MIL, HOLES" at 13268.98,5539.71 h60
  text "+/-" at 12876.52,5539 h60
  text "+/-" at 13730.52,5539 h60
  text "REGISTRATION TOLERANCES:" at 11360.75,5534 h60
  text "METAL" at 12560.52,5534 h60
  text "5" at 13136.72,5534 h60
  text "3" at 13969.72,5534 h60
  text "MIL" at 14085.98,5534 h60
  text "MATERIAL:" at 11330.98,5324.54 h60
  text "FR-4 High Tg" at 12317.42,5184.21 h60
  text "FR-408" at 11751.98,5175.64 h60
  text "OTHER" at 13239.98,5175.64 h60
  text "X" at 11598.52,5175 h60
  text "63 MIL (1.6mm) +/-10%" at 12072.08,5012.92 h60
  text "THICKNESS:" at 11405.75,5008.64 h60
  text "X" at 11943.92,5008.64 h60
  text "OTHER" at 13356.98,5008.64 h60
  text "TOLERANCE:" at 11405.75,4850.64 h60
  text "X" at 12245.05,4850.64 h60
  text "ANSI IPC-6012 TYPE 3 CLASS 2" at 12432,4850.64 h60
  text "OTHER +/-" at 12431.98,4694.64 h60
  text "BOW & TWIST:" at 11405.75,4537.64 h60
  text "X" at 12245.05,4537.64 h60
  text "ANSI IPC-6012 TYPE 3 CLASS 2" at 12432,4537.64 h60
  text "OTHER +/-" at 12431.98,4379.13 h60
  text "COPPER THICKNESS (FINISHED):" at 11330.98,4243.64 h60
  text "1.4MIL (1oz)" at 12210.98,4090.92 h60
  text "2MIL (1.4oz)" at 12977.98,4090.92 h60
  text "2.8MIL (2oz)" at 13704.98,4090.92 h60
  text "OUTER:" at 11687.98,4086.64 h60
  text "X" at 12082.52,4086 h60
  text "1.4MIL (1oz)" at 12210.98,3933.92 h60
  text "2.8MIL (2oz)" at 12977.98,3933.92 h60
  text "N/A" at 13704.52,3934.29 h60
  text "INNER SIGNAL:" at 11398.9,3929.64 h60
  text "X" at 12083.94,3929.64 h60
  text "DRILLING:" at 11330.98,3790.64 h60
  text "REFERENCE:" at 11405.75,3673.64 h60
  text "X" at 12053.98,3673.64 h60
  text "AS SHOWN" at 12240.98,3673.64 h60
  text "X" at 12954.98,3673.64 h60
  text "NC_DRILL FILES" at 13091.98,3673.64 h60
  text "PTH MIN COPPER THICKNESS:" at 11405.75,3515.64 h60
  text "X" at 12755.98,3515.64 h60
  text "1MIL" at 12892.98,3515.64 h60
  text "OTHER" at 13389.98,3515.64 h60
  text "BOARD FINISH:" at 11330.98,3356.64 h60
  text "SILKSCREEN:" at 11486.2,3238.64 h60
  text "X" at 12434.98,3238.64 h60
  text "TOP" at 12560.98,3238.64 h60
  text "X" at 12944.98,3238.64 h60
  text "BOTTOM" at 13071.98,3238.64 h60
  text "SILKSCREEN COLOR:" at 11486.2,3071.64 h60
  text "X" at 12433.94,3071.64 h60
  text "WHITE" at 12560.98,3071.64 h60
  text "OTHER" at 13071.98,3071.64 h60
  text "SOLDER RESIST COLOR:" at 11486.2,2901.64 h60
  text "X" at 12053.94,2742.44 h60
  text "GREEN" at 12180.98,2742.44 h60
  text "BLUE" at 12771.98,2742.44 h60
  text "OTHER" at 13309.98,2742.44 h60
  text "IMMERSION GOLD (ENIG)" at 12391.98,2553.92 h60
  text "ENEPIG" at 13729.52,2550.64 h60
  text "SURFACE FINISH:" at 11330.98,2549.64 h60
  text "X" at 12205.03,2549.64 h60
  text "IMM. TIN/SILVER OR EQUIV" at 11660.52,2392.64 h60
  text "OTHER" at 13091.98,2392.64 h60
  text "ARRAY/PANEL:" at 11330.98,2213.64 h60
  text "CUT AND TRIM PER MECH LAYER 1" at 12391.98,2209.35 h60
  text "N.C. ROUTE" at 12391.98,2057.64 h60
  text "X" at 13070.98,2057.64 h60
  text "V. SCORE" at 13257.98,2057.64 h60
  text "CERTIFICATION:" at 11330.98,1920.64 h60
  text "MATERIALS AND WORKMANSHIP FOR ALL PCBS" at 12055.98,1920.64 h60
  text "TO MEET OR EXCEED THE REQUIREMENTS OF:" at 12055.98,1822.64 h60
  text "X" at 11682.48,1686.13 h60
  text "ANSI IPC-A-600F CLASS ->" at 11821.48,1686.13 h60
  text "X" at 13460.54,1686.13 h60
  text "2" at 13579.48,1686.14 h60
  text "1" at 13264.48,1684.64 h60
  text "3" at 13933.48,1684.64 h60
  text "X" at 11684.54,1526.64 h60
  text "UL 94V-0" at 11821.48,1526.64 h60
  text "X" at 12496.54,1526.64 h60
  text "RoHS" at 12633.48,1526.64 h60
  text "OTHER" at 13277.88,1526.64 h60
  text "PER ORDER" at 13674.94,1526.64 h60
  text "ADDITIONAL REQUIREMENTS:" at 11330.98,1385.64 h60
  text "VIA TENTING:" at 12805.52,1290 h60
  text "X" at 13593.81,1290.11 h60
  text "YES" at 13377.19,1280.92 h60
  text "NO" at 13771.99,1280.69 h60
  text "MICROSECTION:" at 11405.75,1270.64 h60
  text "YES" at 12311.48,1270.64 h60
  text "REQUIRED" at 13172.98,1114.49 h60
  text "BARE BOARD ELEC. TEST:" at 11405.75,1111.64 h60
  text "NONE" at 12711.48,1111.64 h60
  text "X" at 13045.98,1111.64 h60
  text "PER ORDER" at 13764.98,1111.64 h60
  text "MANUFACTURER'S UL:" at 11405.75,954.64 h60
  text "RAIL" at 12571.48,950.35 h60
  text "METAL" at 13063.29,950.35 h60
  text "X" at 13438.52,950 h60
  text "SILK" at 13574.98,950.35 h60
M11 Gerber Information:
  lines w10: -293.48,-930.17 6306.52,-930.17 ; -293.48,-726.83 6308.52,-726.83 ; -293.48,-523.5 -293.48,-1133.5 3711.52,-1133.5 6308.52,-1133.5 6308.52,-523.5 -292.98,-523.5 -292.98,-1133.5 1282.52,-1133.5 ; 2171.52,-1133.5 2171.52,-523.5 ; 3438.52,-726.83 3438.52,-523.5 ; 4278.52,-726.83 4278.52,-523.5 ; 4900.52,-1140 4900.52,-937.17
  text "ALL ARTWORK VIEWED FROM TOP SIDE" at -229.98,-655.67 h60
  text "BOARD #:" at 2246.52,-655.67 h60
  text ".PRJ_Number" at 2792.02,-655.67 h60
  text "SVN REV:" at 4474.52,-655.67 h60
  text ".VersionControl_RevNumber" at 4980.52,-655.67 h60
  text "REV:" at 3560.52,-667 h60
  text ".PCB_Rev" at 3896.52,-667 h60
  text "LAYER NAME =" at -229.98,-858.49 h60
  text "PLOT NAME =" at -229.98,-1064.34 h60
  text ".plot_File_Name" at 575.52,-1064.34 h60
  text "GENERATED    :" at 2248.52,-1064.34 h60
  text ".Print_Date" at 3118.02,-1064.34 h60
  text ".Print_Time" at 3847.02,-1064.34 h60
  text "TEXAS INSTRUMENTS" at 5111.52,-1064.34 h60
M12 Stackup:
  lines w6: 11333.28,7641.3 14212.1,7641.3 ; 11333.28,7745.7 14212.1,7745.7 ; 11273.28,6973.68 ccw(c11307.28,6973.68) 11307.28,6939.68 14238.1,6939.68 ccw(c14238.1,6973.68) 14272.1,6973.68 14272.1,7837.17 ccw(c14238.1,7837.17) 14238.1,7871.17 11307.28,7871.17 ccw(c11307.28,7837.17) 11273.28,7837.17 11273.28,6973.68
  text "Layer Stack Up Detail for: TIDA-00247.PcbDoc" at 11333.28,7773.04 h48
  text "Layer" at 11333.28,7706.7 h24
  text "Gerber" at 12338.7,7706.7 h24
  text "Copper" at 13011.83,7706.7 h24
  text "Dielectric" at 13724.14,7706.7 h24
  text "Name" at 11333.28,7658.7 h24
  text "Document" at 12338.7,7658.7 h24
  text "Thickness" at 13011.83,7658.7 h24
  text "Material" at 13724.14,7658.7 h24
  text "Top Solder Mask" at 11333.28,7589.79 h34
  text "(.GTS)" at 12338.7,7589.79 h34
  text "Solder Resist" at 13724.14,7589.79 h34
  text "Top Layer" at 11333.28,7492.76 h34
  text "(.GTL)" at 12338.7,7492.76 h34
  text "1.4mil" at 13011.83,7492.76 h34
  text "FR-4" at 13724.14,7444.24 h34
  text "GND" at 11333.28,7395.73 h34
  text "(.G1)" at 12338.7,7395.73 h34
  text "1.4mil" at 13011.83,7395.73 h34
  text "FR-4" at 13724.14,7347.21 h34
  text "VCC" at 11333.28,7298.7 h34
  text "(.G2)" at 12338.7,7298.7 h34
  text "1.4mil" at 13011.83,7298.7 h34
  text "FR-4" at 13724.14,7250.18 h34
  text "Bottom Layer" at 11333.28,7201.67 h34
  text "(.GBL)" at 12338.7,7201.67 h34
  text "1.4mil" at 13011.83,7201.67 h34
  text "Bottom Solder Mask" at 11333.28,7104.64 h34
  text "(.GBS)" at 12338.7,7104.64 h34
  text "Solder Resist" at 13724.14,7104.64 h34
M13 Component Bodies Top:
  text ".Layer_Name" at 575.52,-858.49 h60
M14 Component Bodies Bottom:
  text ".Layer_Name" at 575.52,-858.49 h60
M15 Courtyards Top:
  text ".Layer_Name" at 575.52,-858.49 h60
M16 Courtyards Bottom:
  text ".Layer_Name" at 575.52,-858.49 h60
Drill Drawing:
  text ".LEgend" at 2860,975 h60
  text "DRILL TOLERANCE" at 2870,535 h60
  text "EXCEPT 7.874,12 MIL ALL OTHERS HAVE +/-3 MILS TOLERANCE" at 2864,430 h60
  text "FOR 7.874 MIL DRILL +0/-7.874 MIL" at 2867,327 h60
  text "FOR 12 MIL DRILL :+0 /-12 MIL" at 2860,230 h60
  text ".Layer_Name" at 575.52,-858.49 h60

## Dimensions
0,2250 to 550,2250 on M1 Board Outline
550,0 to 550,2250 on M1 Board Outline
